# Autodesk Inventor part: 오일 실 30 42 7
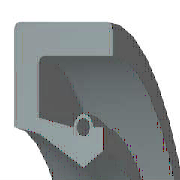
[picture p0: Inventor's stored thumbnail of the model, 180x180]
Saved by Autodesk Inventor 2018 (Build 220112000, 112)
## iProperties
IsCustomPart: 1
Created: 2012-02
Part Number: 오일 실 30 42 7
Material: 고무
Description: 오일 실 - 스프링 장착, 금속 케이스 SM
Document SubType Name: Modeling
Standard: JIS B 2402
Designer: mdu-01
Standards Organization: JIS
Language: ko-KR
Size Designation: 30 42 7 A
Categories: <MemberInstance><Categories><Category DisplayName="샤프트 부품" InternalName="7f7aeb1f-a693-4053-b835-cee3144e0d98" Mnemonic="SHFT"><Category DisplayName="실링" Intern
Density: 0.93 g/cm^3
Appearance: Rubber-Black
Author: mdu-01
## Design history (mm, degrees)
body "Solid1"
revolve "회전1" stored, may be unused: angle "d33" = 360 deg
fillet "모깎기1" dims "d34" = 0.35 (= 0.05 x b)
chamfer "모따기1" distance "d35" = 0.7 (= 0.1 x b); stored, may be unused: second distance "d36" = 0.35 (= 0.05 x b), angle "d41" = 45 deg
sketch "스케치2"
  geometry: L1 (16.457, -5.158)-(17.021, -7); L2 (15.857, -4.55)-(16.457, -5.158); L3 (15, -1.75)-(15.857, -4.55); L4 (15.8, -0.875)-(15, -1.75); L5 (17.141, -0.875)-(15.8, -0.875); L6 (17.141, -1.575)-(17.141, -0.875); L7 (17.141, -5.25)-(17.141, -2.975); L8 (18.6, -5.25)-(17.141, -5.25); L9 (19.8, -1.75)-(18.6, -5.25); L10 (19.8, 0)-(19.8, -1.75); L11 (21, 0)-(19.8, 0); L12 (21, -7)-(21, 0); L13 (17.021, -7)-(21, -7); L14 (0, -9.6)-(0, 1.6) reference; L15 (28, 0)-(14, 0) reference; A1 r 0.7 centre (17.141, -2.275) between (17.141, -2.975) and (17.141, -1.575)
  constraints: 26 end point, 4 horizontal, 4 vertical, 2 point on circle, 1 centre point, 1 collinear, 1 parallel
  dimensions: "d2" = 7 distance of L12.start L11.start (= b); "d4" = 0.875 vertical distance of L10.start L5.start (= 0.125 x b); "d6" = 1.2 distance of L11.start L10.start (= 0.1 x dd - 0.1 x Diam); "d8" = 1.75 distance of L10.start L9.start (= 0.25 x b); "d10" = 1.75 vertical distance of L8.start L1.end (= 0.25 x b); "d12" = 1.2 horizontal distance of L9.start L8.start (= 0.1 x dd - 0.1 x Diam); "d14" = 0.7 radius of A1 (= 0.1 x b); "d16" = 0 horizontal distance of A1.centre L7.end; "d18" = 0.7 distance of L6.start L5.start (= 0.1 x b); "d20" = 0.8 horizontal distance of L4.start L3.start (= 0.0666667 x dd - 0.0666667 x Diam); "d22" = 0.12 horizontal distance of L7.start L1.end (= 0.01 x dd - 0.01 x Diam); "d24" = 0.875 vertical distance of L4.start L3.start (= 0.125 x b); "d26" = 2.8 vertical distance of L3.start L2.start (= 0.4 x b); "d28" = 0.85714 horizontal distance of L3.start L2.start (= 0.0714286 x dd - 0.0714286 x Diam); "d30" = 1.84211 vertical distance of L1.start L1.end (= 0.263158 x b); "d32" = 0.6 horizontal distance of L2.start L1.start (= 0.05 x dd - 0.05 x Diam); "d37" = 0 distance between parallel lines of L15 L11; "d38" = 21 distance between parallel lines of L14 L12 (= 0.5 x dd); "d39" = 15 distance from line of L14 L3.start (= 0.5 x Diam)
other parameters: "dd" = 42 [user parameter; used in 7 equation terms], "b" = 7 [user parameter; used in 12 equation terms], "d1" = 8 (derived), "d3" = 1 (derived), "d5" = 2 (derived), "d7" = 2 (derived), "d9" = 2 (derived), "d11" = 2 (derived), "d13" = 0.8 (derived), "d15" = 0 (derived), "d17" = 0.8 (derived), "d19" = 1.33333 (derived), "d21" = 0.2 (derived), "d23" = 1 (derived), "d25" = 3.2 (derived), "d27" = 1.42857 (derived), "d29" = 2.10526 (derived), "d31" = 1 (derived), "d40" = 0
